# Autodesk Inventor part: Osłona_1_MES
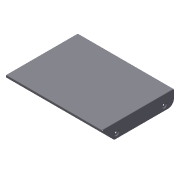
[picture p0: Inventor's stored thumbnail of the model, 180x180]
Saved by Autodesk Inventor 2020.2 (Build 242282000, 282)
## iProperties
Created: 2011-10
Part Number: Osłona_1_MES
Material: Stal
Document SubType Name: Konstrukcja blachowa
Designer: F.Stasiak
Density: 7.85 g/cm^3
Sheet Metal Rule: Blacha stalowa 2.5 mm/Okrągły
Mass: 8089.94 g
Surface Area: 13831.1 cm^2
Volume: 1030.57 cm^3
Appearance: Metal-Stal
Catalog Web Link: www.expertbooks.pl
Manager: www.cadconsulting.pl
Company: Fabian Stasiak CAD Consulting
Author: F.Stasiak
Subject: Zbiór ćwiczeń. Autodesk Inventor 2020. Kurs Professional
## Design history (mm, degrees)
node "Powierzchnia1"
  sketch "Szkic1"
    geometry: L1 (0, 0)-(800, 0); L2 (800, 0)-(800, 600); L3 (800, 600)-(0, 600); L4 (0, 600)-(0, 0)
    constraints: 8 end point, 2 parallel, 1 horizontal, 1 perpendicular
    dimensions: "d0" = 800 distance of L3.end L2.end; "d1" = 600 distance of L2.end L1.end
node "Kołnierz4"
sketch "Szkic9"
  geometry: L1 (0, 600)-(115, 600) reference; L2 (0, 600)-(0, 0) reference; L3 (0, 0)-(115, 0) reference; L4 (40, 520)-(40, 120); 3 further points
  constraints: 2 coincident, 2 end point, 1 perpendicular
  dimensions: "d69" = 400 distance of L4.start L4.end; "d70" = 40 distance between parallel lines of L2 L4; "d71" = 80 distance from line of L1 point (40, 520)
feature "iFeature5:1" sketch "Szkic9"
feature "Zaokrąglenie narożnika2" dims "d74" = 50
feature "Fazowanie narożnika2" dims "d75" = 100, "d76" = 6, angle "d77" = 45 deg
hole "Otwór2" diameter "d80" = 12; stored, may be unused: countersink angle "d84" = 90 deg, drill point angle "d86" = 118 deg; dims "d78" = 10, "d79" = 10, "d81" = 6, "d82" = 4, "d83" = 2, "d85" = 2.5 (= Grubość)
hole "Otwór3" diameter "d89" = 12; stored, may be unused: countersink angle "d93" = 90 deg, drill point angle "d95" = 118 deg; dims "d87" = 10, "d88" = 10, "d90" = 6, "d91" = 4, "d92" = 2, "d94" = 2.5 (= Grubość)
node "Płaszczyzna konstrukcyjna1"
mirror "Odbicie lustrzane1"
node "Kołnierz5"
node "Kołnierz6"
sketch "Szkic12"
  geometry: C1 r 18.83 at (-40, 420) reference; C2 r 18.83 at (-40, 20) reference; 1 further point
feature "iFeature5:2" sketch "Szkic12"
hole "Otwór4" diameter "d120" = 12; stored, may be unused: countersink angle "d124" = 90 deg, drill point angle "d126" = 118 deg; dims "d118" = 10, "d119" = 10, "d121" = 6, "d122" = 4, "d123" = 2, "d125" = 2.5 (= Grubość)
hole "Otwór5" diameter "d129" = 12; stored, may be unused: countersink angle "d133" = 90 deg, drill point angle "d135" = 118 deg; dims "d127" = 10, "d128" = 10, "d130" = 6, "d131" = 4, "d132" = 2, "d134" = 2.5 (= Grubość)
node "Bryła1"
feature "Płyta1" dims "d160" = 2.5 (= Grubość)
sketch "Szkic7"
  geometry: L1 (0, -120)-(600, -120); L2 (600, -120)-(600, 0); 1 other entity
  constraints: 4 end point, 4 other
feature "Płyta5" dims "d56" = 2.5 (= SzerokośćGięciaPodcięcia), "d57" = 1.25 (= GłębokośćGięciaPodcięcia), "d58" = 5 (= MinimalnaPozostałość), "d59" = 2.5 (= PromieńGięcia), "d60" = 120, "d61" = 90 deg, "d62" = 2.5 (= PromieńGięcia), "d63" = 10 (= RozmiarPodcięciaNarożnika), "d64" = 2.5 (= Wielk_odstępu), "d65" = 2.5 (= Rozmiar_promienia_Jacobiego), "d160" = 2.5 (= Grubość), "OdstępPołączenia" = 0.01
feature "Gięcie4" dims "d56" = 2.5 (= SzerokośćGięciaPodcięcia), "d57" = 1.25 (= GłębokośćGięciaPodcięcia), "d58" = 5 (= MinimalnaPozostałość), "d59" = 2.5 (= PromieńGięcia), "d60" = 120, "d61" = 90 deg, "d62" = 2.5 (= PromieńGięcia), "d160" = 2.5 (= Grubość), "OdstępPołączenia" = 0.01
feature "Narożnik4" dims "d60" = 120, "d61" = 90 deg, "d63" = 10 (= RozmiarPodcięciaNarożnika), "d64" = 2.5 (= Wielk_odstępu), "d65" = 2.5 (= Rozmiar_promienia_Jacobiego)
sketch "Szkic10"
  geometry: L1 through (0, 0) direction (-2.74e-49, -1); L2 (0, -20)-(795, -20); L3 (795, -20)-(795, 0); 1 other entity
  constraints: 5 end point, 2 vertical, 2 other
feature "Płyta6" dims "d96" = 2.5 (= SzerokośćGięciaPodcięcia), "d97" = 1.25 (= GłębokośćGięciaPodcięcia), "d98" = 5 (= MinimalnaPozostałość), "d99" = 2.5 (= PromieńGięcia), "d100" = 20, "d101" = 90 deg, "d102" = 2.5 (= PromieńGięcia), "d103" = 10 (= RozmiarPodcięciaNarożnika), "d104" = 2.5 (= Wielk_odstępu), "d105" = 2.5 (= Rozmiar_promienia_Jacobiego), "d160" = 2.5 (= Grubość), "OdstępPołączenia" = 0.01
feature "Gięcie5" dims "d96" = 2.5 (= SzerokośćGięciaPodcięcia), "d97" = 1.25 (= GłębokośćGięciaPodcięcia), "d98" = 5 (= MinimalnaPozostałość), "d99" = 2.5 (= PromieńGięcia), "d100" = 20, "d101" = 90 deg, "d102" = 2.5 (= PromieńGięcia), "d160" = 2.5 (= Grubość), "OdstępPołączenia" = 0.01
feature "Narożnik5" dims "d100" = 20, "d101" = 90 deg, "d103" = 10 (= RozmiarPodcięciaNarożnika), "d104" = 2.5 (= Wielk_odstępu), "d105" = 2.5 (= Rozmiar_promienia_Jacobiego)
sketch "Szkic11"
  geometry: L1 (0, -80)-(795, -80); L2 (795, -80)-(795, 0); 1 other entity
  constraints: 4 end point, 4 other
feature "Płyta7" dims "d106" = 2.5 (= SzerokośćGięciaPodcięcia), "d107" = 1.25 (= GłębokośćGięciaPodcięcia), "d108" = 5 (= MinimalnaPozostałość), "d109" = 2.5 (= PromieńGięcia), "d110" = 80, "d111" = 90 deg, "d112" = 2.5 (= PromieńGięcia), "d113" = 10 (= RozmiarPodcięciaNarożnika), "d114" = 2.5 (= Wielk_odstępu), "d115" = 2.5 (= Rozmiar_promienia_Jacobiego), "d160" = 2.5 (= Grubość), "OdstępPołączenia" = 0.01
feature "Gięcie6" dims "d106" = 2.5 (= SzerokośćGięciaPodcięcia), "d107" = 1.25 (= GłębokośćGięciaPodcięcia), "d108" = 5 (= MinimalnaPozostałość), "d109" = 2.5 (= PromieńGięcia), "d110" = 80, "d111" = 90 deg, "d112" = 2.5 (= PromieńGięcia), "d160" = 2.5 (= Grubość), "OdstępPołączenia" = 0.01
feature "Narożnik6" dims "d110" = 80, "d111" = 90 deg, "d113" = 10 (= RozmiarPodcięciaNarożnika), "d114" = 2.5 (= Wielk_odstępu), "d115" = 2.5 (= Rozmiar_promienia_Jacobiego)
other parameters: "Grubość" = 2.5 (derived), "WspółczynnikK" = 4.4, "PromieńGięcia" = 2.5 (= Grubość), "SzerokośćGięciaPodcięcia" = 2.5 (= Grubość), "GłębokośćGięciaPodcięcia" = 1.25 (= 0.5 x Grubość), "MinimalnaPozostałość" = 5 (= 2 x Grubość), "PromieńPrzejścia" = 2.5 (= PromieńGięcia), "Rozmiar_promienia_Jacobiego" = 2.5 (= PromieńGięcia), "Wielk_odstępu" = 2.5 (= Grubość), "d2" = 2.5 (= PromieńGięcia), "d73" = 0, "d117" = 0
